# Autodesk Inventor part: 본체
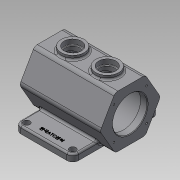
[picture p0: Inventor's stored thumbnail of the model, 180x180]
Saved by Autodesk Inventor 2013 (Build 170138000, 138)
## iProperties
Created: 2021-06
Part Number: 본체
Material: 일반
Document SubType Name: Modeling
Designer: hana-cad36
Density: 1 g/cm^3
Author: hana-cad36
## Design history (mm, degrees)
sketch "스케치1"
  geometry: L1 (52.5, 0)-(26.25, -45.466); L2 (26.25, -45.466)-(-26.25, -45.466); L3 (-26.25, -45.466)-(-52.5, 0); L4 (-52.5, 0)-(-26.25, 45.466); L5 (-26.25, 45.466)-(26.25, 45.466); L6 (26.25, 45.466)-(52.5, 0); 2 further points
  constraints: 12 end point, 1 coincident, 1 horizontal alignment, 13 other
  dimensions: "d10" = 105 distance of L1.start L3.end
extrude "돌출1" new body sketch "스케치1" distance "d1" = 65; taper "d2" = 0 deg; dims "d75" = 75, "d76" = 0
fillet "모깎기1" dims "d59" = 8
node "작업 평면1"
sketch "스케치2"
  geometry: L1 (-40, 75)-(40, 75); L2 (50, 65)-(50, -65); L3 (40, -75)-(-40, -75); L4 (-50, -65)-(-50, 65); A1 r 10 centre (-40, 65) between (-40, 75) and (-50, 65); A2 r 10 centre (40, 65) between (50, 65) and (40, 75); A3 r 10 centre (-40, -65) between (-50, -65) and (-40, -75); A4 r 10 centre (40, -65) between (40, -75) and (50, -65); 5 further points
  constraints: 8 end point, 8 point on circle, 8 tangent, 4 centre point, 4 point on line, 3 equal radius, 2 midpoint, 2 parallel, 1 horizontal, 1 horizontal alignment, 1 perpendicular, 1 vertical alignment
  dimensions: "d4" = 150 distance of point (-50, -75) point (-50, 75); "d6" = 10 radius of A1; "d7" = 100 distance between parallel lines of L4 L2
extrude "돌출2" join sketch "스케치2" distance "d8" = 12; taper "d9" = 0 deg
node "작업 평면2"
sketch "스케치3"
  geometry: L1 (-75, -21.631)-(-75, 21.631) reference; C1 r 20 at (-35, 0); C2 r 20 at (25, 0); 3 further points
  constraints: 2 centre point, 2 horizontal alignment
  dimensions: "d12" = 40 distance from line of L1 C1.centre; "d13" = 60 distance of C2.centre C1.centre; "d14" = 40 diameter of C1; "d15" = 40 diameter of C2
extrude "돌출3" join sketch "스케치3" stored distance "d16" = 12; taper "d17" = 0 deg
sketch "스케치4"
  geometry: L1 (-75, 26.25)-(-75, -26.25) reference; L2 (65, -26.25)-(65, 26.25) reference; L3 (-75, 30)-(-63, 30); L4 (-63, 30)-(-63, 32.5); L5 (-58, 37.5)-(48, 37.5); L6 (53, 32.5)-(53, 30); L7 (53, 30)-(65, 30); L8 (-75, 0)-(65, 0); L9 (65, 0)-(65, 30); L10 (-75, 30)-(-75, 0); A1 r 5 centre (-58, 32.5) between (-58, 37.5) and (-63, 32.5); A2 r 5 centre (48, 32.5) between (53, 32.5) and (48, 37.5); 3 further points
  constraints: 16 end point, 6 point on line, 4 perpendicular, 4 point on circle, 4 tangent, 2 centre point, 2 midpoint, 2 parallel, 1 collinear, 1 equal radius
  dimensions: "d18" = 12 distance of L6.end L7.end; "d20" = 12 distance of L3.start L3.end; "d24" = 60 diameter of L3 L8; "d25" = 75 diameter of L5 L8; "d26" = 60 diameter of L7 L8; "d58" = 5 radius of A1
revolve "회전1" sketch "스케치4" stored, may be unused: angle "d27" = 90 deg
sketch "스케치5"
  geometry: C1 r 20 at (0, 0) reference; C2 r 20 at (-60, 0) reference; 1 further point
hole "구멍1" sketch "스케치5" at (-60, 0), (0, 0) diameter "d28" = 25; stored, may be unused: countersink angle "d32" = 90 deg, drill point angle "d34" = 118 deg; dims "d29" = 6, "d30" = 30, "d31" = 8, "d33" = 8
sketch "스케치6"
  geometry: C1 r 30 at (0, 0) reference; 1 further point
  constraints: 1 horizontal alignment
  dimensions: "d35" = 40 distance of C1.centre point (-40, 0)
hole "구멍2" sketch "스케치6" at (-40, 0) diameter "d36" = 3.242; stored, may be unused: countersink angle "d40" = 90 deg, drill point angle "d42" = 118 deg; dims "d37" = 8, "d38" = 30, "d39" = 8, "d41" = 10
sketch "스케치7"
  geometry: L1 (45.466, -26.25)-(45.466, 26.25) reference; L2 (0, 0)-(30, 0); L3 (0, 0)-(28.284, 28.284)
  constraints: 4 end point, 1 horizontal alignment, 1 perpendicular, 1 other
  dimensions: "d46" = 45 deg angle of L2 L3; "d47" = 40 distance of L2.start L3.end
hole "구멍3" sketch "스케치7" at (28.284, 28.284) diameter "d48" = 3.242; stored, may be unused: countersink angle "d52" = 90 deg, drill point angle "d54" = 118 deg; dims "d49" = 8, "d50" = 30, "d51" = 8, "d53" = 10
chamfer "모따기1" distance "d60" = 1; stored, may be unused: second distance "d61" = 2, angle "d62" = 45 deg
sketch "스케치8"
  geometry: A1 r 10 centre (-40, -65) between (-50, -65) and (-40, -75) reference; A2 r 10 centre (40, -65) between (40, -75) and (50, -65) reference; 1 further point
hole "구멍4" sketch "스케치8" at (-40, -65), (40, -65) diameter "d64" = 11; stored, may be unused: countersink angle "d68" = 90 deg, drill point angle "d70" = 118 deg; dims "d65" = 8, "d66" = 30, "d67" = 8, "d69" = 10
fillet "모깎기2" dims "d63" = 3
fillet "모깎기3" dims "d71" = 3
chamfer "모따기2" distance "d72" = 1; stored, may be unused: second distance "d73" = 2, angle "d74" = 45 deg
node "작업 평면3"
sketch "스케치9"
  geometry: L1 (-50, -32.293)-(-50, -65) reference; L2 (-40, -75)-(40, -75) reference; L3 (-50, 65)-(-50, 32.293) reference; L4 (40, 75)-(-40, 75) reference; 2 further points
  constraints: 1 other
  dimensions: "d84" = 50 distance from line of L3 point (0, 61); "d85" = 14 distance from line of L4 point (0, 61)
feature "엠보싱1" sketch "스케치9" dims "d80" = 0.5, "d81" = 0
node "솔리드1"
pattern_circular "원형 패턴1" dims angle "d44" = 360 deg
pattern_circular "원형 패턴2" dims angle "d56" = 360 deg
mirror "대칭1"
other parameters: "d11" = 52.5, "d77" = 10.75
